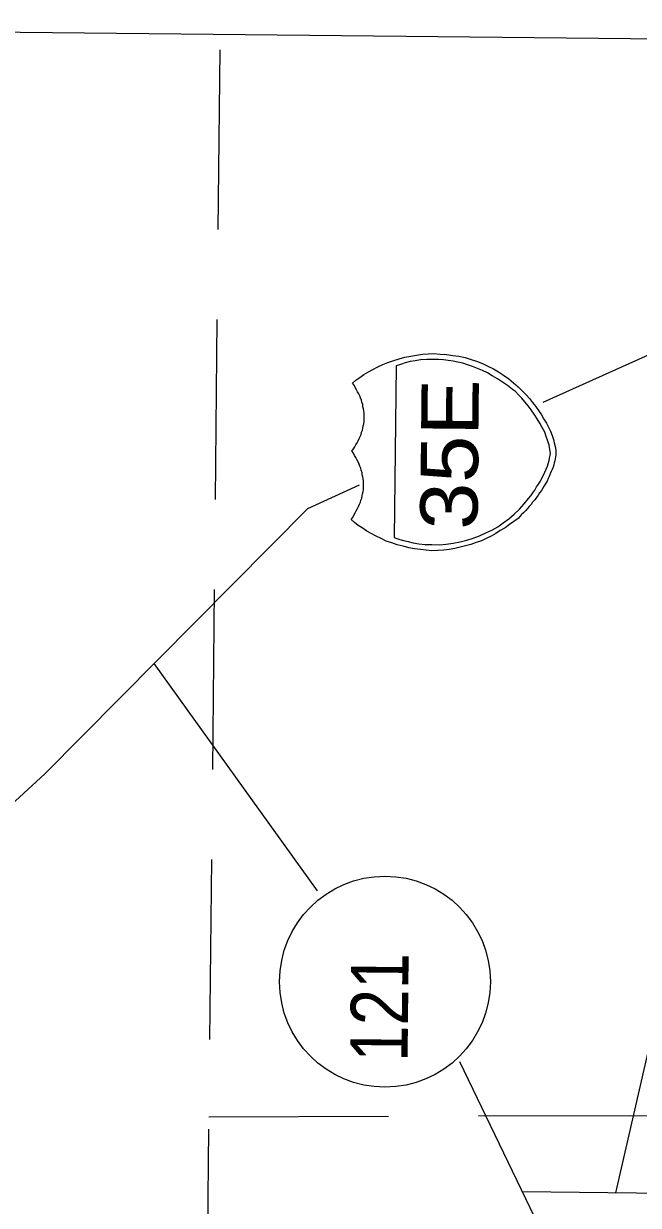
# Model space of a CAD drawing. Extents: x 2356576 to 2377878, y 6966390 to 6990634.
# Drawn here: x 2365706.5 to 2365779.3, y 6969120 to 6969259.9 of the extents above; entities that cross this region are included whole.
import ezdxf

# ---------------------------------------------------------------- set-up
doc = ezdxf.new("R2010")
doc.units = 0
doc.header["$LTSCALE"] = 7.1
doc.linetypes.add('MEDIUM_DASHED', pattern=[4.5, 3, -1.5])
doc.layers.add('19', color=7, linetype='Continuous', lineweight=13)
doc.layers.add('8', color=7, linetype='Continuous', lineweight=13)

msp = doc.modelspace()

# ---------------------------------------------------------------- linework, layer by layer
at = {"layer": '19', "linetype": 'MEDIUM_DASHED'}
for p, q in [((2365729.713, 6969256.812), (2365723.521, 6968659.188)), ((2365728.404, 6969130.515), (2366103.06, 6969131.614))]:
    msp.add_line(p, q, dxfattribs=at)
at = {"layer": '19'}
for p, q in [((2365741.31, 6969157.263), (2365721.94, 6969184.165)), ((2365856.653, 6969120.666), (2365765.574, 6969121.609))]:
    msp.add_line(p, q, dxfattribs=at)
at = {"layer": '19', "lineweight": 25}
for points in [[(2365597.072, 6968660.498), (2366217.375, 6968654.072), (2366223.585, 6969253.468), (2365603.282, 6969259.894)], [(2365768.042, 6969215.073), (2365794.66, 6969227.038), (2365842.946, 6969237.006), (2365878.319, 6969257.045)], [(2365601.809, 6969117.726), (2365630.768, 6969127.146), (2365677.914, 6969142.527), (2365708.992, 6969171.098), (2365740.131, 6969202.521), (2365746.28, 6969205.306)], [(2365796.054, 6969190.929), (2365783.684, 6969152.235), (2365776.613, 6969121.495)]]:
    msp.add_lwpolyline(points, dxfattribs=at)
at = {"layer": '19'}
for points in [[(2365745.972, 6969210.289), (2365746.122, 6969210.528), (2365746.245, 6969210.798), (2365746.339, 6969211.005), (2365746.462, 6969211.276), (2365746.493, 6969211.544), (2365746.615, 6969211.783), (2365746.65, 6969212.022), (2365746.712, 6969212.294), (2365746.775, 6969212.533), (2365746.806, 6969212.801), (2365746.808, 6969213.041), (2365746.811, 6969213.313), (2365746.813, 6969213.553), (2365746.816, 6969213.793), (2365746.791, 6969214.093), (2365746.733, 6969214.301), (2365746.676, 6969214.542), (2365746.647, 6969214.814), (2365746.529, 6969215.084), (2365746.504, 6969215.324), (2365746.387, 6969215.597), (2365746.297, 6969215.838), (2365746.18, 6969216.079), (2365746.034, 6969216.321), (2365745.917, 6969216.562), (2365745.767, 6969216.832), (2365745.622, 6969217.105), (2365745.445, 6969217.347), (2365745.836, 6969217.703), (2365746.292, 6969218.026), (2365746.775, 6969218.353), (2365747.319, 6969218.676), (2365747.862, 6969218.97), (2365748.433, 6969219.264), (2365749.035, 6969219.53), (2365749.638, 6969219.792), (2365750.333, 6969220.024), (2365750.963, 6969220.23), (2365751.657, 6969220.403), (2365752.346, 6969220.544), (2365753.039, 6969220.656), (2365753.729, 6969220.769), (2365754.389, 6969220.795), (2365755.081, 6969220.847), (2365755.829, 6969220.78), (2365756.608, 6969220.74), (2365757.327, 6969220.612), (2365758.046, 6969220.517), (2365758.769, 6969220.389), (2365759.486, 6969220.142), (2365760.144, 6969219.923), (2365760.83, 6969219.676), (2365761.486, 6969219.369), (2365762.143, 6969219.034), (2365762.739, 6969218.668), (2365763.336, 6969218.302), (2365763.963, 6969217.843), (2365764.526, 6969217.389), (2365765.061, 6969216.904), (2365765.628, 6969216.358), (2365766.011, 6969215.962), (2365766.427, 6969215.538), (2365766.782, 6969215.054), (2365767.137, 6969214.602), (2365767.492, 6969214.086), (2365767.819, 6969213.575), (2365768.114, 6969213.092), (2365768.409, 6969212.609), (2365768.644, 6969212.126), (2365768.879, 6969211.644), (2365769.082, 6969211.162), (2365769.257, 6969210.68), (2365769.345, 6969210.259), (2365769.46, 6969209.838), (2365769.516, 6969209.417), (2365769.512, 6969209.057)], [(2365769.512, 6969209.057), (2365769.51, 6969208.817), (2365769.507, 6969208.605), (2365769.445, 6969208.366), (2365769.411, 6969208.158), (2365769.348, 6969207.919), (2365769.286, 6969207.679), (2365769.195, 6969207.38), (2365769.1, 6969207.109), (2365768.977, 6969206.871), (2365768.855, 6969206.604), (2365768.732, 6969206.305), (2365768.609, 6969206.034), (2365768.486, 6969205.736), (2365768.335, 6969205.497), (2365768.152, 6969205.199), (2365767.997, 6969204.901), (2365767.814, 6969204.635), (2365767.603, 6969204.337), (2365767.42, 6969204.067), (2365767.238, 6969203.801), (2365767.023, 6969203.531), (2365766.78, 6969203.265), (2365766.597, 6969202.995), (2365766.387, 6969202.757), (2365766.172, 6969202.491), (2365765.961, 6969202.254), (2365765.719, 6969202.016), (2365765.477, 6969201.807), (2365765.262, 6969201.541), (2365765.052, 6969201.331), (2365764.81, 6969201.154), (2365764.536, 6969200.948), (2365764.052, 6969200.593), (2365763.508, 6969200.207), (2365762.937, 6969199.885), (2365762.421, 6969199.558), (2365761.85, 6969199.236), (2365761.275, 6969198.942), (2365760.704, 6969198.676), (2365760.07, 6969198.474), (2365759.468, 6969198.241), (2365758.838, 6969198.067), (2365758.204, 6969197.922), (2365757.571, 6969197.78), (2365756.909, 6969197.635), (2365756.249, 6969197.582), (2365755.528, 6969197.529), (2365754.84, 6969197.509), (2365754.148, 6969197.576), (2365753.489, 6969197.643), (2365752.802, 6969197.738), (2365752.111, 6969197.865), (2365751.425, 6969198.024), (2365750.735, 6969198.211), (2365750.109, 6969198.426), (2365749.419, 6969198.645), (2365748.822, 6969198.951), (2365748.225, 6969199.225), (2365747.66, 6969199.531), (2365747.123, 6969199.837), (2365746.587, 6969200.202), (2365746.11, 6969200.479), (2365745.662, 6969200.844), (2365745.277, 6969201.208), (2365745.46, 6969201.446), (2365745.611, 6969201.712), (2365745.766, 6969201.983), (2365745.888, 6969202.222), (2365746.039, 6969202.488), (2365746.161, 6969202.727), (2365746.256, 6969202.998), (2365746.379, 6969203.237), (2365746.409, 6969203.476), (2365746.532, 6969203.715), (2365746.566, 6969203.983), (2365746.629, 6969204.222), (2365746.692, 6969204.521), (2365746.722, 6969204.733), (2365746.725, 6969204.973), (2365746.728, 6969205.273), (2365746.73, 6969205.513), (2365746.733, 6969205.753), (2365746.707, 6969206.021), (2365746.65, 6969206.262), (2365746.592, 6969206.503), (2365746.563, 6969206.743), (2365746.446, 6969207.044), (2365746.421, 6969207.284), (2365746.303, 6969207.526), (2365746.213, 6969207.767), (2365746.096, 6969208.04), (2365745.951, 6969208.309), (2365745.834, 6969208.55), (2365745.684, 6969208.792), (2365745.539, 6969209.034), (2365745.361, 6969209.307), (2365745.544, 6969209.546), (2365745.694, 6969209.784), (2365745.849, 6969210.05), (2365745.972, 6969210.289)], [(2365779.211, 6969091.102), (2365770.717, 6969105.291), (2365768.57, 6969115.398), (2365758.173, 6969136.987)]]:
    msp.add_lwpolyline(points, dxfattribs=at)
msp.add_lwpolyline([(2365750.594, 6969219.394), (2365750.384, 6969199.083), (2365750.682, 6969198.96), (2365751.041, 6969198.836), (2365751.46, 6969198.712), (2365752.031, 6969198.586), (2365752.629, 6969198.432), (2365753.288, 6969198.305), (2365754.035, 6969198.237), (2365754.847, 6969198.229), (2365755.687, 6969198.22), (2365756.528, 6969198.271), (2365757.369, 6969198.382), (2365758.179, 6969198.554), (2365758.965, 6969198.754), (2365759.715, 6969198.986), (2365760.498, 6969199.25), (2365761.222, 6969199.603), (2365761.945, 6969199.955), (2365762.641, 6969200.336), (2365763.306, 6969200.809), (2365763.971, 6969201.282), (2365764.605, 6969201.848), (2365765.211, 6969202.441), (2365765.758, 6969203.036), (2365766.304, 6969203.69), (2365766.579, 6969203.987), (2365766.791, 6969204.345), (2365767.035, 6969204.671), (2365767.251, 6969205.06), (2365767.462, 6969205.386), (2365767.706, 6969205.744), (2365767.889, 6969206.102), (2365768.073, 6969206.46), (2365768.229, 6969206.818), (2365768.38, 6969207.149), (2365768.536, 6969207.507), (2365768.627, 6969207.806), (2365768.723, 6969208.165), (2365768.786, 6969208.465), (2365768.849, 6969208.764), (2365768.88, 6969209.064), (2365768.824, 6969209.484), (2365768.742, 6969209.993), (2365768.595, 6969210.475), (2365768.392, 6969211.017), (2365768.218, 6969211.531), (2365767.923, 6969212.074), (2365767.629, 6969212.585), (2365767.334, 6969213.128), (2365766.98, 6969213.672), (2365766.593, 6969214.188), (2365766.238, 6969214.671), (2365765.855, 6969215.123), (2365765.499, 6969215.579), (2365765.111, 6969215.971), (2365764.755, 6969216.335), (2365764.398, 6969216.579), (2365763.803, 6969217.065), (2365763.207, 6969217.463), (2365762.611, 6969217.857), (2365761.987, 6969218.224), (2365761.418, 6969218.562), (2365760.821, 6969218.836), (2365760.255, 6969219.082), (2365759.658, 6969219.3), (2365759.06, 6969219.514), (2365758.518, 6969219.7), (2365757.919, 6969219.826), (2365757.352, 6969219.924), (2365756.781, 6969220.018), (2365756.214, 6969220.084), (2365755.642, 6969220.122), (2365755.074, 6969220.127), (2365754.262, 6969220.136), (2365753.513, 6969220.084), (2365752.852, 6969219.97), (2365752.251, 6969219.885), (2365751.678, 6969219.743), (2365751.256, 6969219.595), (2365750.895, 6969219.479)], close=True, dxfattribs=at)
msp.add_circle((2365749.284, 6969146.494), 12.486, dxfattribs=at)
at = {"layer": '8', "linetype": 'MEDIUM_DASHED'}
for p, q in [((2365729.713, 6969256.812), (2365723.521, 6968659.188)), ((2365728.404, 6969130.515), (2366103.06, 6969131.614))]:
    msp.add_line(p, q, dxfattribs=at)
at = {"layer": '8'}
for p, q in [((2365741.31, 6969157.263), (2365721.94, 6969184.165)), ((2365856.653, 6969120.666), (2365765.574, 6969121.609))]:
    msp.add_line(p, q, dxfattribs=at)
at = {"layer": '8', "lineweight": 25}
for points in [[(2365597.072, 6968660.498), (2366217.375, 6968654.072), (2366223.585, 6969253.468), (2365603.282, 6969259.894)], [(2365768.042, 6969215.073), (2365794.66, 6969227.038), (2365842.946, 6969237.006), (2365878.319, 6969257.045)], [(2365601.809, 6969117.726), (2365630.768, 6969127.146), (2365677.914, 6969142.527), (2365708.992, 6969171.098), (2365740.131, 6969202.521), (2365746.28, 6969205.306)], [(2365796.054, 6969190.929), (2365783.684, 6969152.235), (2365776.613, 6969121.495)]]:
    msp.add_lwpolyline(points, dxfattribs=at)
at = {"layer": '8'}
for points in [[(2365745.972, 6969210.289), (2365746.122, 6969210.528), (2365746.245, 6969210.798), (2365746.339, 6969211.005), (2365746.462, 6969211.276), (2365746.493, 6969211.544), (2365746.615, 6969211.783), (2365746.65, 6969212.022), (2365746.712, 6969212.294), (2365746.775, 6969212.533), (2365746.806, 6969212.801), (2365746.808, 6969213.041), (2365746.811, 6969213.313), (2365746.813, 6969213.553), (2365746.816, 6969213.793), (2365746.791, 6969214.093), (2365746.733, 6969214.301), (2365746.676, 6969214.542), (2365746.647, 6969214.814), (2365746.529, 6969215.084), (2365746.504, 6969215.324), (2365746.387, 6969215.597), (2365746.297, 6969215.838), (2365746.18, 6969216.079), (2365746.034, 6969216.321), (2365745.917, 6969216.562), (2365745.767, 6969216.832), (2365745.622, 6969217.105), (2365745.445, 6969217.347), (2365745.836, 6969217.703), (2365746.292, 6969218.026), (2365746.775, 6969218.353), (2365747.319, 6969218.676), (2365747.862, 6969218.97), (2365748.433, 6969219.264), (2365749.035, 6969219.53), (2365749.638, 6969219.792), (2365750.333, 6969220.024), (2365750.963, 6969220.23), (2365751.657, 6969220.403), (2365752.346, 6969220.544), (2365753.039, 6969220.656), (2365753.729, 6969220.769), (2365754.389, 6969220.795), (2365755.081, 6969220.847), (2365755.829, 6969220.78), (2365756.608, 6969220.74), (2365757.327, 6969220.612), (2365758.046, 6969220.517), (2365758.769, 6969220.389), (2365759.486, 6969220.142), (2365760.144, 6969219.923), (2365760.83, 6969219.676), (2365761.486, 6969219.369), (2365762.143, 6969219.034), (2365762.739, 6969218.668), (2365763.336, 6969218.302), (2365763.963, 6969217.843), (2365764.526, 6969217.389), (2365765.061, 6969216.904), (2365765.628, 6969216.358), (2365766.011, 6969215.962), (2365766.427, 6969215.538), (2365766.782, 6969215.054), (2365767.137, 6969214.602), (2365767.492, 6969214.086), (2365767.819, 6969213.575), (2365768.114, 6969213.092), (2365768.409, 6969212.609), (2365768.644, 6969212.126), (2365768.879, 6969211.644), (2365769.082, 6969211.162), (2365769.257, 6969210.68), (2365769.345, 6969210.259), (2365769.46, 6969209.838), (2365769.516, 6969209.417), (2365769.512, 6969209.057)], [(2365769.512, 6969209.057), (2365769.51, 6969208.817), (2365769.507, 6969208.605), (2365769.445, 6969208.366), (2365769.411, 6969208.158), (2365769.348, 6969207.919), (2365769.286, 6969207.679), (2365769.195, 6969207.38), (2365769.1, 6969207.109), (2365768.977, 6969206.871), (2365768.855, 6969206.604), (2365768.732, 6969206.305), (2365768.609, 6969206.034), (2365768.486, 6969205.736), (2365768.335, 6969205.497), (2365768.152, 6969205.199), (2365767.997, 6969204.901), (2365767.814, 6969204.635), (2365767.603, 6969204.337), (2365767.42, 6969204.067), (2365767.238, 6969203.801), (2365767.023, 6969203.531), (2365766.78, 6969203.265), (2365766.597, 6969202.995), (2365766.387, 6969202.757), (2365766.172, 6969202.491), (2365765.961, 6969202.254), (2365765.719, 6969202.016), (2365765.477, 6969201.807), (2365765.262, 6969201.541), (2365765.052, 6969201.331), (2365764.81, 6969201.154), (2365764.536, 6969200.948), (2365764.052, 6969200.593), (2365763.508, 6969200.207), (2365762.937, 6969199.885), (2365762.421, 6969199.558), (2365761.85, 6969199.236), (2365761.275, 6969198.942), (2365760.704, 6969198.676), (2365760.07, 6969198.474), (2365759.468, 6969198.241), (2365758.838, 6969198.067), (2365758.204, 6969197.922), (2365757.571, 6969197.78), (2365756.909, 6969197.635), (2365756.249, 6969197.582), (2365755.528, 6969197.529), (2365754.84, 6969197.509), (2365754.148, 6969197.576), (2365753.489, 6969197.643), (2365752.802, 6969197.738), (2365752.111, 6969197.865), (2365751.425, 6969198.024), (2365750.735, 6969198.211), (2365750.109, 6969198.426), (2365749.419, 6969198.645), (2365748.822, 6969198.951), (2365748.225, 6969199.225), (2365747.66, 6969199.531), (2365747.123, 6969199.837), (2365746.587, 6969200.202), (2365746.11, 6969200.479), (2365745.662, 6969200.844), (2365745.277, 6969201.208), (2365745.46, 6969201.446), (2365745.611, 6969201.712), (2365745.766, 6969201.983), (2365745.888, 6969202.222), (2365746.039, 6969202.488), (2365746.161, 6969202.727), (2365746.256, 6969202.998), (2365746.379, 6969203.237), (2365746.409, 6969203.476), (2365746.532, 6969203.715), (2365746.566, 6969203.983), (2365746.629, 6969204.222), (2365746.692, 6969204.521), (2365746.722, 6969204.733), (2365746.725, 6969204.973), (2365746.728, 6969205.273), (2365746.73, 6969205.513), (2365746.733, 6969205.753), (2365746.707, 6969206.021), (2365746.65, 6969206.262), (2365746.592, 6969206.503), (2365746.563, 6969206.743), (2365746.446, 6969207.044), (2365746.421, 6969207.284), (2365746.303, 6969207.526), (2365746.213, 6969207.767), (2365746.096, 6969208.04), (2365745.951, 6969208.309), (2365745.834, 6969208.55), (2365745.684, 6969208.792), (2365745.539, 6969209.034), (2365745.361, 6969209.307), (2365745.544, 6969209.546), (2365745.694, 6969209.784), (2365745.849, 6969210.05), (2365745.972, 6969210.289)], [(2365779.211, 6969091.102), (2365770.717, 6969105.291), (2365768.57, 6969115.398), (2365758.173, 6969136.987)]]:
    msp.add_lwpolyline(points, dxfattribs=at)
msp.add_lwpolyline([(2365750.594, 6969219.394), (2365750.384, 6969199.083), (2365750.682, 6969198.96), (2365751.041, 6969198.836), (2365751.46, 6969198.712), (2365752.031, 6969198.586), (2365752.629, 6969198.432), (2365753.288, 6969198.305), (2365754.035, 6969198.237), (2365754.847, 6969198.229), (2365755.687, 6969198.22), (2365756.528, 6969198.271), (2365757.369, 6969198.382), (2365758.179, 6969198.554), (2365758.965, 6969198.754), (2365759.715, 6969198.986), (2365760.498, 6969199.25), (2365761.222, 6969199.603), (2365761.945, 6969199.955), (2365762.641, 6969200.336), (2365763.306, 6969200.809), (2365763.971, 6969201.282), (2365764.605, 6969201.848), (2365765.211, 6969202.441), (2365765.758, 6969203.036), (2365766.304, 6969203.69), (2365766.579, 6969203.987), (2365766.791, 6969204.345), (2365767.035, 6969204.671), (2365767.251, 6969205.06), (2365767.462, 6969205.386), (2365767.706, 6969205.744), (2365767.889, 6969206.102), (2365768.073, 6969206.46), (2365768.229, 6969206.818), (2365768.38, 6969207.149), (2365768.536, 6969207.507), (2365768.627, 6969207.806), (2365768.723, 6969208.165), (2365768.786, 6969208.465), (2365768.849, 6969208.764), (2365768.88, 6969209.064), (2365768.824, 6969209.484), (2365768.742, 6969209.993), (2365768.595, 6969210.475), (2365768.392, 6969211.017), (2365768.218, 6969211.531), (2365767.923, 6969212.074), (2365767.629, 6969212.585), (2365767.334, 6969213.128), (2365766.98, 6969213.672), (2365766.593, 6969214.188), (2365766.238, 6969214.671), (2365765.855, 6969215.123), (2365765.499, 6969215.579), (2365765.111, 6969215.971), (2365764.755, 6969216.335), (2365764.398, 6969216.579), (2365763.803, 6969217.065), (2365763.207, 6969217.463), (2365762.611, 6969217.857), (2365761.987, 6969218.224), (2365761.418, 6969218.562), (2365760.821, 6969218.836), (2365760.255, 6969219.082), (2365759.658, 6969219.3), (2365759.06, 6969219.514), (2365758.518, 6969219.7), (2365757.919, 6969219.826), (2365757.352, 6969219.924), (2365756.781, 6969220.018), (2365756.214, 6969220.084), (2365755.642, 6969220.122), (2365755.074, 6969220.127), (2365754.262, 6969220.136), (2365753.513, 6969220.084), (2365752.852, 6969219.97), (2365752.251, 6969219.885), (2365751.678, 6969219.743), (2365751.256, 6969219.595), (2365750.895, 6969219.479)], close=True, dxfattribs=at)
msp.add_circle((2365749.284, 6969146.494), 12.486, dxfattribs=at)

# ---------------------------------------------------------------- texts
at = {"layer": '19'}
for s, width, p in [('35E', 1.1, (2365760.238, 6969199.973)), ('121', 0.85, (2365751.961, 6969136.991))]:
    msp.add_text(s, height=6.798, rotation=89.406, dxfattribs=dict(at, width=width)).set_placement(p)
at = {"layer": '8'}
for s, width, p in [('35E', 1.1, (2365760.238, 6969199.973)), ('121', 0.85, (2365751.961, 6969136.991))]:
    msp.add_text(s, height=6.798, rotation=89.406, dxfattribs=dict(at, width=width)).set_placement(p)

doc.saveas('drawing.dxf')
